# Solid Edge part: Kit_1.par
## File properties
Sűrűség: 0,000 kg/m^3
Pontosság: 0,990
Author: bmolnar
Last saved by: bmolnar
Revision: 78
Username: bmolnar
Dokumentum tartalom típus: 0
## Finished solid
Body 1: solid body, 44 faces, 61 edges, 28 vertices.
  Faces by surface: cone 15, cylinder 14, plane 11, torus 4
  Edges by curve: circle 47, line 14
Bounding box of the edges (mm; curved faces can reach further): 85.500 x 85.350 x 17.850, from (-42.75, -40.85, 88.15) to (42.75, 44.5, 106).
Cylindrical faces by radius (mm): R1.5 x2, R3 x4, R10.3 x1, R10.95 x1, R11.5 x1, R12.5 x1, R22 x1, R37.5 x1, R40.85 x1, R42.75 x1
Conical faces (half-angle, radius in mm at the cone's reference point): 7 deg R11.7695 x1, 14 deg R10.15 x1, 14 deg R10.557 x1, 17 deg R10.15 x1, 23 deg R10.9211 x1, 42.5 deg R10.137 x1, 45 deg R11.2 x1, 45 deg R11.65 x1, 45 deg R21.25 x1, 45 deg R40.75 x2, 60 deg R26.6072 x1, 84 deg R10.512 x1, 85 deg R12.1625 x1, 87 deg R10.2157 x1
Toroidal faces (ring radius, tube radius in mm): R10.9008 r0.225 x1, R11.3914 r0.325 x1, R22.8 r0.8 x1, R31.2144 r0.8 x1
Planar faces by outward normal: +z 7, -z 2, oblique 2
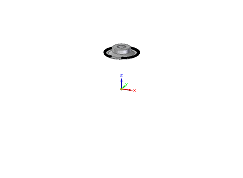
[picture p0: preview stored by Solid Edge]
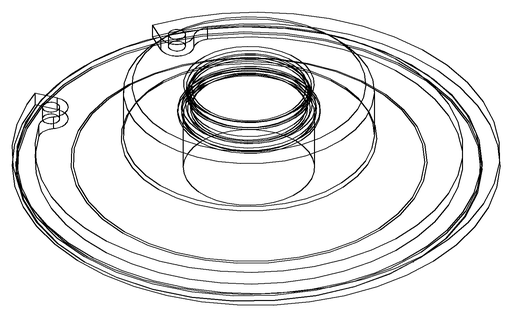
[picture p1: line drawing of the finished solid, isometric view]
